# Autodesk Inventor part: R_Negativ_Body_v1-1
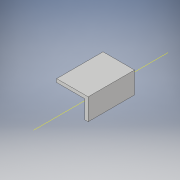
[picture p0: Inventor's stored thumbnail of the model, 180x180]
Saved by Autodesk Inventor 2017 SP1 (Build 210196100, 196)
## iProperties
Part Number: R_Negativ_Body_v1-1
Material: Generisch
Document SubType Name: Modeling
Designer: haesner
Density: 1 g/cm^3
Appearance: Vorgabe
Part Number: R_Negativ_Body_v1-1_3D-Druck
Author: haesner
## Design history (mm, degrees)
sketch "Skizze1"
  geometry: L1 (0, 9.5)-(0, -9.5); L2 (0, -50.282)-(0, 43.534) reference; A1 r 9.5 centre (0, 0) between (0, 9.5) and (0, -9.5); 1 further point
  constraints: 2 end point, 2 point on circle, 1 centre point, 1 coincident, 1 collinear, 1 vertical
  dimensions: "d0" = 9.5 radius of A1
extrude "Extrusion1" new body sketch "Skizze1" distance "d1" = 9; taper "d2" = 0 deg
sketch "Skizze2"
  geometry: L1 (-1, 30.132)-(-1, -36.879); L2 (0, 43.534)-(0, -50.282) reference; 1 further point
  constraints: 2 end point, 1 vertical
  dimensions: "d3" = 1 distance between parallel lines of L2 L1
workplane "Arbeitsebene1"
  workaxis "Arbeitsachse1"
feature "Trennen1"
sketch "Skizze3"
  geometry: L1 (-1, 9.447)-(-1, -9.447) reference; L2 (0, -9.5)-(0, 9.5) reference; A1 r 9.5 centre (0, 0) between (-1, -9.447) and (0, -9.5) reference; A2 r 9.5 centre (0, 0) between (0, 9.5) and (-1, 9.447) reference; 1 further point
extrude "Extrusion2" join sketch "Skizze3" distance "d5" = 1; taper "d6" = 0 deg
sketch "Skizze4"
  geometry: L1 (0, -9.5)-(0, 9.5) reference; A1 r 9.5 centre (0, 0) between (-1, 9.447) and (-1, -9.447) reference; A2 r 9.5 centre (0, 0) between (0, 9.5) and (-1, 9.447) reference; A3 r 9.5 centre (0, 0) between (-1, -9.447) and (0, -9.5) reference; 1 further point
extrude "Extrusion3" join sketch "Skizze4" distance "d7" = 1; taper "d8" = 0 deg
sketch "Skizze5"
  geometry: L1 (-17, 14)-(0, 14); L2 (0, 14)-(0, -14); L3 (0, -14)-(-17, -14); L4 (-17, -14)-(-17, 14); L5 (0, -50.282)-(0, 43.534) reference; L6 (-20.4, 0)-(3.4, 0) reference; 1 further point
  constraints: 8 end point, 2 parallel, 1 collinear, 1 horizontal, 1 perpendicular, 1 other
  dimensions: "d9" = 28 distance of L1.end L2.end; "d10" = 17 distance of L1.start L1.end
extrude "Extrusion4" join sketch "Skizze5" distance "d11" = 2; taper "d12" = 0 deg
sketch "Skizze6"
  geometry: L1 (0, 23.5)-(-13, 23.5); L2 (-13, 23.5)-(-13, -4.5); L3 (-13, -4.5)-(0, -4.5); L4 (0, -4.5)-(0, 23.5); L5 (0, -40.782)-(0, 53.034) reference; L6 (-13, -4.5)-(-13, 23.5) reference; L7 (2.6, 9.5)-(-15.6, 9.5) reference; L8 (0, 0)-(0, 19) reference; 1 further point
  constraints: 8 end point, 2 collinear, 2 parallel, 1 horizontal, 1 perpendicular, 1 other
  dimensions: "d14" = 28 distance of L3.end L1.start
extrude "Extrusion5" join sketch "Skizze6" distance "d15" = 2; taper "d16" = 0 deg
node "Volumenkörper1"
node "Projizierte Kontur1"
other parameters: "d4" = 40 deg
